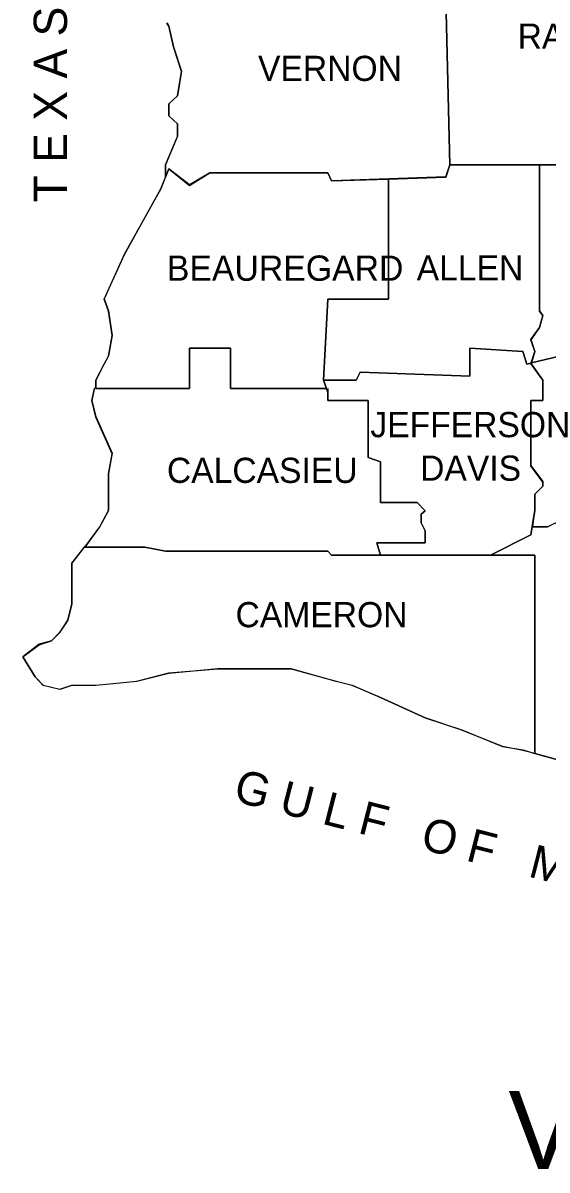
# Model space of a CAD drawing. Extents: x 0.23 to 2.82, y 0.04 to 1.79.
# Drawn here: x 2.2229 to 2.3204, y 1.3806 to 1.594 of the extents above; entities that cross this region are included whole.
import ezdxf

# ---------------------------------------------------------------- set-up
doc = ezdxf.new("R2010")
doc.units = 0
for name, color, linetype in [('Dist03', 7, 'Continuous'), ('Dist07', 7, 'Continuous'), ('Dist08', 7, 'Continuous'), ('Standard Info', 7, 'Continuous')]:
    doc.layers.add(name, color=color, linetype=linetype)

msp = doc.modelspace()

# ---------------------------------------------------------------- linework, layer by layer
at = {"layer": 'Dist03'}
for points in [[(2.3469, 1.56308), (2.3454, 1.56308), (2.3454, 1.56758), (2.3439, 1.56917), (2.3424, 1.57067), (2.3424, 1.57292), (2.34015, 1.57292), (2.33782, 1.57292), (2.33557, 1.57367), (2.33482, 1.57592), (2.33407, 1.57592), (2.33257, 1.57517), (2.33182, 1.57367), (2.33024, 1.57217), (2.32799, 1.57067), (2.32649, 1.56758), (2.31899, 1.56758)], [(2.31899, 1.56758), (2.31899, 1.54042), (2.31965, 1.53958), (2.31899, 1.53733), (2.3174, 1.53508), (2.31815, 1.53283), (2.3174, 1.53058)], [(2.31732, 1.53075), (2.31965, 1.5275), (2.31965, 1.526), (2.31965, 1.52375), (2.3174, 1.52375), (2.3174, 1.51167), (2.31965, 1.50867), (2.31965, 1.50783), (2.31815, 1.50633), (2.31815, 1.50333), (2.3174, 1.49875), (2.3099, 1.495)], [(2.3099, 1.495), (2.31815, 1.495), (2.31815, 1.45833)], [(2.31815, 1.45808), (2.32424, 1.45642), (2.33257, 1.45725), (2.34015, 1.45492), (2.34165, 1.45492), (2.3469, 1.45642), (2.34765, 1.45642)]]:
    msp.add_lwpolyline(points, dxfattribs=at)
at = {"layer": 'Dist07'}
msp.add_line((2.23649, 1.5275), (2.23649, 1.526), dxfattribs=at)
for points in [[(2.30232, 1.56758), (2.30157, 1.56533), (2.28032, 1.56458), (2.27965, 1.56608), (2.25765, 1.56608), (2.2539, 1.56383), (2.25007, 1.56683), (2.2494, 1.56533)], [(2.31899, 1.56758), (2.30232, 1.56758)], [(2.3174, 1.53058), (2.31815, 1.53283), (2.3174, 1.53508), (2.31899, 1.53733), (2.31965, 1.53958), (2.31899, 1.54042), (2.31899, 1.56758)], [(2.2494, 1.56533), (2.24857, 1.56308)], [(2.24857, 1.56308), (2.24182, 1.551), (2.23799, 1.54267), (2.23882, 1.54042), (2.23949, 1.53583), (2.23882, 1.53208), (2.23799, 1.53058), (2.23649, 1.5275), (2.23649, 1.52742)], [(2.3099, 1.495), (2.3174, 1.49875), (2.31815, 1.50333), (2.31815, 1.50633), (2.31965, 1.50783), (2.31965, 1.50867), (2.3174, 1.51167), (2.3174, 1.52375), (2.31965, 1.52375), (2.31965, 1.526), (2.31965, 1.5275), (2.31732, 1.53075)], [(2.23624, 1.52608), (2.23574, 1.52375), (2.23649, 1.52075), (2.23949, 1.51392), (2.23882, 1.51017), (2.23882, 1.50333), (2.23724, 1.50033), (2.2344, 1.4965)], [(2.23432, 1.4965), (2.23199, 1.4935)], [(2.23199, 1.4935), (2.23199, 1.49275), (2.23199, 1.489), (2.23199, 1.4875), (2.23199, 1.48592), (2.23124, 1.48292), (2.22974, 1.48067), (2.22824, 1.47908), (2.2259, 1.47842), (2.2229, 1.47608), (2.22515, 1.47233), (2.22665, 1.47083), (2.22974, 1.47008), (2.23199, 1.47083), (2.23649, 1.47083), (2.24407, 1.47158), (2.25007, 1.47308), (2.25915, 1.47383), (2.26824, 1.47383), (2.27282, 1.47383), (2.28115, 1.47158), (2.28415, 1.47083), (2.2894, 1.4685), (2.29774, 1.46475), (2.30457, 1.4625), (2.31215, 1.45942), (2.3159, 1.45875), (2.31815, 1.45808)], [(2.31815, 1.45833), (2.31815, 1.495), (2.3099, 1.495)]]:
    msp.add_lwpolyline(points, dxfattribs=at)
at = {"layer": 'Dist08'}
for points in [[(2.24965, 1.59392), (2.25007, 1.59333), (2.2509, 1.5895), (2.2524, 1.585), (2.25165, 1.58042), (2.25007, 1.57892), (2.25007, 1.57667), (2.25165, 1.57517), (2.25165, 1.57292), (2.2494, 1.56758), (2.2494, 1.56533)], [(2.30232, 1.56758), (2.32649, 1.56758), (2.32799, 1.57067), (2.33024, 1.57217), (2.33182, 1.57367), (2.33257, 1.57517), (2.33407, 1.57592), (2.33482, 1.57592), (2.33557, 1.57367), (2.33782, 1.57292), (2.34015, 1.57292), (2.3424, 1.57292)], [(2.2494, 1.56533), (2.25007, 1.56683), (2.2539, 1.56383), (2.25765, 1.56608), (2.27965, 1.56608), (2.28032, 1.56458), (2.30157, 1.56533), (2.30232, 1.56758)]]:
    msp.add_lwpolyline(points, dxfattribs=at)
at = {"layer": 'Standard Info'}
for p, q in [((2.24965, 1.59383), (2.2499, 1.594)), ((2.23649, 1.526), (2.23649, 1.5275)), ((2.31765, 1.50025), (2.31774, 1.50025))]:
    msp.add_line(p, q, dxfattribs=at)
for points in [[(2.29249, 1.60517), (2.29249, 1.60392), (2.29849, 1.60392), (2.29849, 1.59858), (2.30157, 1.59858), (2.30232, 1.56758)], [(2.29249, 1.60517), (2.29249, 1.60392), (2.29849, 1.60392), (2.29849, 1.59858), (2.30157, 1.59858), (2.30232, 1.56758)], [(2.30232, 1.56758), (2.30157, 1.59858), (2.29849, 1.59858), (2.29849, 1.60392), (2.29249, 1.60392), (2.29249, 1.60517)], [(2.29249, 1.60508), (2.29249, 1.60392), (2.29849, 1.60392), (2.29849, 1.59858), (2.30157, 1.59858), (2.30232, 1.56758)], [(2.2494, 1.56525), (2.2494, 1.56758), (2.25165, 1.57283), (2.25165, 1.57517), (2.25007, 1.57667), (2.25007, 1.57892), (2.25165, 1.58042), (2.2524, 1.58492), (2.2509, 1.5895), (2.25007, 1.59333), (2.24965, 1.59383)], [(2.3424, 1.57283), (2.34015, 1.57283), (2.33782, 1.57283), (2.33557, 1.57367), (2.33482, 1.57592), (2.33407, 1.57592), (2.33257, 1.57517), (2.33182, 1.57367), (2.33024, 1.57208), (2.32799, 1.57058), (2.32649, 1.56758), (2.30232, 1.56758)], [(2.31899, 1.56758), (2.32649, 1.56758), (2.32799, 1.57058), (2.33024, 1.57208), (2.33182, 1.57367), (2.33257, 1.57517), (2.33407, 1.57592), (2.33482, 1.57592), (2.33557, 1.57367), (2.33782, 1.57283), (2.34015, 1.57283), (2.3424, 1.57283), (2.3424, 1.57058), (2.3439, 1.56908), (2.3454, 1.56758), (2.3454, 1.56308), (2.3469, 1.56308)], [(2.30232, 1.56758), (2.30157, 1.56525), (2.28032, 1.56458), (2.27965, 1.56608), (2.25765, 1.56608), (2.2539, 1.56375), (2.25007, 1.56683), (2.2494, 1.56525)], [(2.2494, 1.56525), (2.25007, 1.56683), (2.2539, 1.56375), (2.25765, 1.56608), (2.27965, 1.56608), (2.28032, 1.56458), (2.2909, 1.56492)], [(2.2909, 1.56492), (2.30157, 1.56525), (2.30232, 1.56758)], [(2.30232, 1.56758), (2.31899, 1.56758)], [(2.3174, 1.5305), (2.31815, 1.53283), (2.3174, 1.535), (2.31899, 1.53733), (2.31965, 1.53958), (2.31899, 1.54033), (2.31899, 1.56758)], [(2.31899, 1.56758), (2.31899, 1.54033), (2.31965, 1.53958), (2.31899, 1.53733), (2.3174, 1.535), (2.31815, 1.53283), (2.31749, 1.53075)], [(2.24857, 1.56308), (2.2494, 1.56525)], [(2.27882, 1.5275), (2.27965, 1.54258), (2.2909, 1.54258), (2.2909, 1.56492)], [(2.2909, 1.56492), (2.2909, 1.54258), (2.27965, 1.54258), (2.27882, 1.5275), (2.2794, 1.526)], [(2.23649, 1.52733), (2.23649, 1.5275), (2.23799, 1.5305), (2.23882, 1.532), (2.23949, 1.53583), (2.23882, 1.54033), (2.23799, 1.54258), (2.24182, 1.55092), (2.24857, 1.56308)], [(2.2794, 1.526), (2.26149, 1.526), (2.26149, 1.5335), (2.2539, 1.5335), (2.2539, 1.526), (2.23649, 1.526)], [(2.23649, 1.526), (2.2539, 1.526), (2.2539, 1.5335), (2.26149, 1.5335), (2.26149, 1.526), (2.2794, 1.526)], [(2.3174, 1.53067), (2.31665, 1.5305), (2.3159, 1.53283), (2.30607, 1.5335), (2.30607, 1.52825), (2.28565, 1.529), (2.2849, 1.5275), (2.27882, 1.5275)], [(2.27882, 1.5275), (2.2849, 1.5275), (2.28565, 1.529), (2.30607, 1.52825), (2.30607, 1.5335), (2.3159, 1.53283), (2.31665, 1.5305), (2.3174, 1.53067)], [(2.32724, 1.532), (2.32274, 1.532), (2.31749, 1.53075)], [(2.31749, 1.53075), (2.32274, 1.532), (2.32799, 1.532), (2.34465, 1.532), (2.34465, 1.52825), (2.34924, 1.52825), (2.34924, 1.52142), (2.35299, 1.51842), (2.35224, 1.51692)], [(2.31732, 1.53067), (2.31965, 1.5275), (2.31965, 1.526), (2.31965, 1.52375), (2.3174, 1.52375), (2.3174, 1.51158), (2.31965, 1.50858), (2.31965, 1.50783), (2.31815, 1.50633), (2.31815, 1.50325), (2.3174, 1.49875), (2.3099, 1.495)], [(2.31774, 1.50025), (2.31815, 1.50325), (2.31815, 1.50633), (2.31965, 1.50783), (2.31965, 1.50858), (2.3174, 1.51158), (2.3174, 1.52375), (2.31965, 1.52375), (2.31965, 1.526), (2.31965, 1.5275), (2.31732, 1.53067)], [(2.27965, 1.52375), (2.27965, 1.52525), (2.27882, 1.5275)], [(2.2344, 1.4965), (2.23724, 1.50025), (2.23882, 1.50325), (2.23882, 1.51008), (2.23949, 1.51383), (2.23649, 1.52067), (2.23574, 1.52375), (2.23624, 1.526)], [(2.27965, 1.526), (2.27965, 1.52375)], [(2.2894, 1.495), (2.28874, 1.49725), (2.29774, 1.49725), (2.29774, 1.4995), (2.29699, 1.501), (2.29699, 1.50258), (2.29774, 1.50325), (2.29624, 1.50475), (2.2894, 1.50475), (2.2894, 1.51233), (2.28715, 1.51317), (2.28715, 1.52375), (2.27965, 1.52375)], [(2.27965, 1.52375), (2.28715, 1.52375), (2.28715, 1.51317), (2.2894, 1.51233), (2.2894, 1.50475), (2.29624, 1.50475), (2.29774, 1.50325), (2.29699, 1.50258), (2.29699, 1.501), (2.29774, 1.4995), (2.29774, 1.49725), (2.28874, 1.49725), (2.2894, 1.495)], [(2.31765, 1.50025), (2.32049, 1.50025), (2.32199, 1.501), (2.32424, 1.4995), (2.32499, 1.4995), (2.32574, 1.49875), (2.32799, 1.49725), (2.32957, 1.4965), (2.33182, 1.4965), (2.33332, 1.4965), (2.33557, 1.498), (2.33632, 1.49875), (2.33707, 1.4995), (2.33857, 1.50175), (2.34015, 1.50325), (2.34165, 1.50408)], [(2.31815, 1.45867), (2.31815, 1.495), (2.3099, 1.495), (2.3174, 1.49875), (2.31765, 1.50025)], [(2.32049, 1.50025), (2.31765, 1.50025)], [(2.23199, 1.4935), (2.23432, 1.49642)], [(2.2894, 1.495), (2.28032, 1.495), (2.27965, 1.49575), (2.2494, 1.49575), (2.24557, 1.4965), (2.23424, 1.4965)], [(2.23424, 1.4965), (2.24557, 1.4965), (2.2494, 1.49575), (2.27965, 1.49575), (2.28032, 1.495), (2.3099, 1.495)], [(2.31815, 1.45808), (2.3159, 1.45867), (2.31215, 1.45942), (2.30457, 1.46242), (2.29774, 1.46475), (2.2894, 1.4685), (2.28415, 1.47075), (2.28115, 1.4715), (2.27282, 1.47383), (2.26824, 1.47383), (2.25915, 1.47383), (2.25007, 1.473), (2.24407, 1.4715), (2.23649, 1.47075), (2.23199, 1.47075), (2.22974, 1.47), (2.22665, 1.47075), (2.22515, 1.47233), (2.2229, 1.47608), (2.2259, 1.47833), (2.22824, 1.47908), (2.22974, 1.48058), (2.23124, 1.48292), (2.23199, 1.48592), (2.23199, 1.48742), (2.23199, 1.48892), (2.23199, 1.49267), (2.23199, 1.4935)], [(2.3099, 1.495), (2.2894, 1.495)], [(2.3099, 1.495), (2.31815, 1.495), (2.31815, 1.45825)], [(2.34765, 1.45642), (2.3469, 1.45642), (2.34165, 1.45492), (2.34015, 1.45492), (2.33257, 1.45717), (2.32424, 1.45642), (2.31815, 1.45808)]]:
    msp.add_lwpolyline(points, dxfattribs=at)

# ---------------------------------------------------------------- texts
for s, rotation, p in [('T E X A S', 90, (2.23111, 1.56058)), ('G U L F   O F   M E X I C O', 345.6507, (2.26182, 1.4493))]:
    msp.add_text(s, height=0.0062, rotation=rotation, dxfattribs=at).set_placement(p)
for s, height, p in [('RAPIDES', 0.004679, (2.31494, 1.58917)), ('VERNON', 0.004679, (2.26664, 1.58317)), ('BEAUREGARD', 0.0047, (2.24968, 1.54601)), ('ALLEN', 0.004679, (2.29616, 1.54608)), ('JEFFERSON', 0.004679, (2.28754, 1.51692)), ('CALCASIEU', 0.004679, (2.24969, 1.50842)), ('DAVIS', 0.004679, (2.2968, 1.50883)), ('CAMERON', 0.004679, (2.26246, 1.48158)), ('VICINITY MAP', 0.0145, (2.31323, 1.38084))]:
    msp.add_text(s, height=height, dxfattribs=at).set_placement(p)

doc.saveas('drawing.dxf')
